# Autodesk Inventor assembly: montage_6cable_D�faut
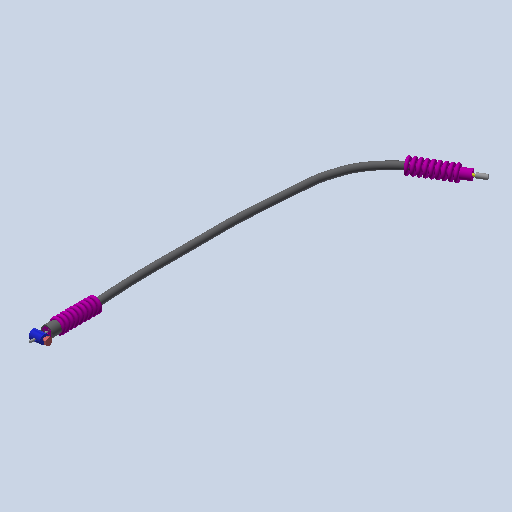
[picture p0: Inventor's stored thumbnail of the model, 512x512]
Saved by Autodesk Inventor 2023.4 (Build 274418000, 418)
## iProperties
Created: 2011-01
Part Number: montage_6cable_D�faut
Document SubType Name: Assembly
Designer: eric
Mass: 9.7659 g
Surface Area: 225.622 cm^2
Volume: 9.7659 cm^3
Density: 1 g/cm^3
Author: eric
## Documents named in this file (6)
- C:\Users\bruno\Documents\1-Cours-2024-25\TSsI\7-Dynamique\chariot de golf\chariot_de_golf\chariot_de_golf_trolem\montage_6cable_Defaut.iam
- C:\Users\bruno\Documents\1-Cours-2024-25\TSsI\7-Dynamique\chariot de golf\chariot_de_golf\chariot_de_golf_trolem\11tube-cable_Defaut.ipt
- C:\Users\bruno\Documents\1-Cours-2024-25\TSsI\7-Dynamique\chariot de golf\chariot_de_golf\chariot_de_golf_trolem\6cable_Defaut.ipt
- C:\Users\bruno\Documents\1-Cours-2024-25\TSsI\7-Dynamique\chariot de golf\chariot_de_golf\chariot_de_golf_trolem\57soufflet_Defaut.ipt
- C:\Users\bruno\Documents\1-Cours-2024-25\TSsI\7-Dynamique\chariot de golf\chariot_de_golf\chariot_de_golf_trolem\10gaine_Defaut.ipt
- C:\Users\bruno\Documents\1-Cours-2024-25\TSsI\7-Dynamique\chariot de golf\chariot_de_golf\chariot_de_golf_trolem\54butee_de cable_Defaut.ipt
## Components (6 placed, 5 different names)
1. 11tube-cable_Defaut:1
2. 6cable_Defaut:1
3. 57soufflet_Defaut:1
4. 57soufflet_Defaut:2
5. 10gaine_Defaut:1
6. 54butee_de cable_Defaut:1
